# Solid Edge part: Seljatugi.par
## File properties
Author: Georg
Template: Iso Part.par
Last saved by: Kalle
Revision: 5
Application: Solid Edge
Accuracy: 0,990
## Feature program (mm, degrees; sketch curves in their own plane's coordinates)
sketch for "unnamed Protrusion 1" plane through (0, 0, 0) normal (0, 0, 1) x-axis (1, 0, 0)
  line (-3, -7.5) -> (3, -7.5)
  line (3, -7.5) -> (3, 7.5)
  line (3, 7.5) -> (-3, 7.5)
  line (-3, 7.5) -> (-3, -7.5)
  dimension (linear) = 3
  dimension (linear) = 3
extrude "unnamed Protrusion 1" add finite 27 along +normal
fillet "Round_1" radius 4
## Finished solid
Body 1: solid body, 7 faces, 15 edges, 10 vertices.
  Faces by surface: plane 6, cylinder 1
  Edges by curve: line 13, circle 2
Bounding box of the edges (mm): 6.000 x 15.000 x 27.000, from (-3, -7.5, 0) to (3, 7.5, 27).
Cylindrical faces by radius (mm): R4 x1
Planar faces by outward normal: +x 1, +y 1, +z 1, -x 1, -y 1, -z 1
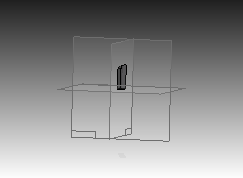
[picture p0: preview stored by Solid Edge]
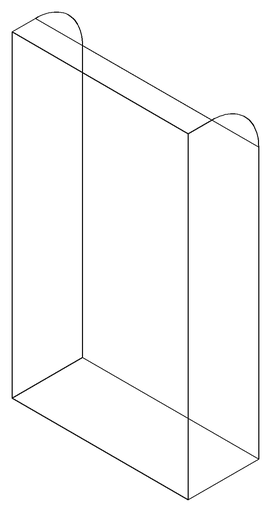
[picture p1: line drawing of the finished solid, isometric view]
